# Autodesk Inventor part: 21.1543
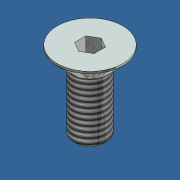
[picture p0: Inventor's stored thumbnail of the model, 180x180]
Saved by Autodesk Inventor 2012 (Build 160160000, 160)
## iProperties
Created: 2006-12
Part Number: 21.1543
Material: Steel, Mild
Description: M5X12 C'SUNK
Document SubType Name: Modeling
Standard: DIN 7991
Designer: Andy Moles
Standards Organization: DIN
Language: en-US
Size Designation: M5x16
Categories: <MemberInstance Version="R10.0.0"><Categories><Category DisplayName="Fasteners" InternalName="e4da775c-781d-43d5-af7c-5136215cf5a6" Mnemonic="FSTN"><Category Di
Density: 7.86 g/cm^3
Mass: 2.35515 g
Surface Area: 3.553 cm^2
Volume: 0.299638 cm^3
Vendor: S
Author: Andy Moles
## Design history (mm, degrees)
node "Sketch1"
node "WorkPoint1"
sketch "Sketch2"
  geometry: L1 (-2.5, -12)-(0, -12); L2 (-2.5, -2.8)-(-2.5, -12); L3 (-5, -0.3)-(-2.5, -2.8); L4 (-5, 0)-(-5, -0.3); L5 (0, 0)-(-5, 0); L6 (0, -12)-(0, 0); L7 (0, -12)-(0, 0); L8 (0, -19.2)-(0, 3.2) reference; L9 (1, 0)-(-6, 0) reference
  constraints: 14 end point, 3 vertical, 2 horizontal
  dimensions: "d1" = 45 deg angle of L3 L6; "d3" = 5 distance of L5.start L4.start (= 0.5 x dk); "d5" = 2.5 distance of L1.start L1.end (= 0.5 x NND); "d7" = 12 distance of L1.end L5.start (= NLG); "ParC" = 0.3 distance of L4.start L3.start; "d22" = 0 distance between parallel lines of L8 L6; "d23" = 0 distance between parallel lines of L9 L5
fillet "Fillet1" dims "d18" = 0.2 (= r)
chamfer "Chamfer1" distance "d19" = 0.4 (= 0.5 x PTC); stored, may be unused: angle "d20" = 45 deg, second distance "d39" = 0.4 (= 0.5 x PTC)
node "MSC_A1"
node "MSC_PF1"
node "MSC_PT1"
body "Solid1"
revolve "Revolution1" stored, may be unused: angle "d8" = 360 deg
sketch "Sketch3"
  geometry: L1 (-1.5, 0.866)-(-1.5, -0.866); L2 (0, 1.732)-(-1.5, 0.866); L3 (1.5, 0.866)-(0, 1.732); L4 (1.5, -0.866)-(1.5, 0.866); L5 (0, -1.732)-(1.5, -0.866); L6 (-1.5, -0.866)-(0, -1.732); C1 r 1.5 at (0, 0); C2 r 2.5 at (0, 0) reference
  constraints: 12 end point, 6 tangent, 2 parallel, 2 vertical, 1 centre point, 1 concentric
  dimensions: "d11" = 3 diameter of C1 (= ParS); "d13" = 120 deg angle of L1 L2; "d15" = 120 deg angle of L6 L1
extrude "Extrusion1" cut sketch "Sketch3" distance "d16" = 2.3 (= ParT); taper "d17" = 0 deg
thread "Thread1" dims "d35" = 0, "b" = 13.5
other parameters: "NND" = 5 [user parameter; used in 2 equation terms], "PTC" = 0.8 [user parameter; used in 2 equation terms], "ParK" = 2.8 [user parameter], "ParS" = 3 [user parameter; used in 1 equation term], "ParT" = 2.3 [user parameter; used in 1 equation term], "r" = 0.2 [user parameter; used in 1 equation term], "NLG" = 12 [user parameter; used in 1 equation term], "d0" = 45 deg (derived), "d2" = 3 (derived), "d4" = 1.5 (derived), "d6" = 8 (derived), "d9" = 0, "d10" = 2 (derived), "d12" = 120 deg (derived), "d14" = 120 deg (derived), "d37" = 0, "d38" = 0, "d40" = 0, "d41" = 0, "d42" = 0, "THREADDIA" = 5 (= NND) [user parameter]
